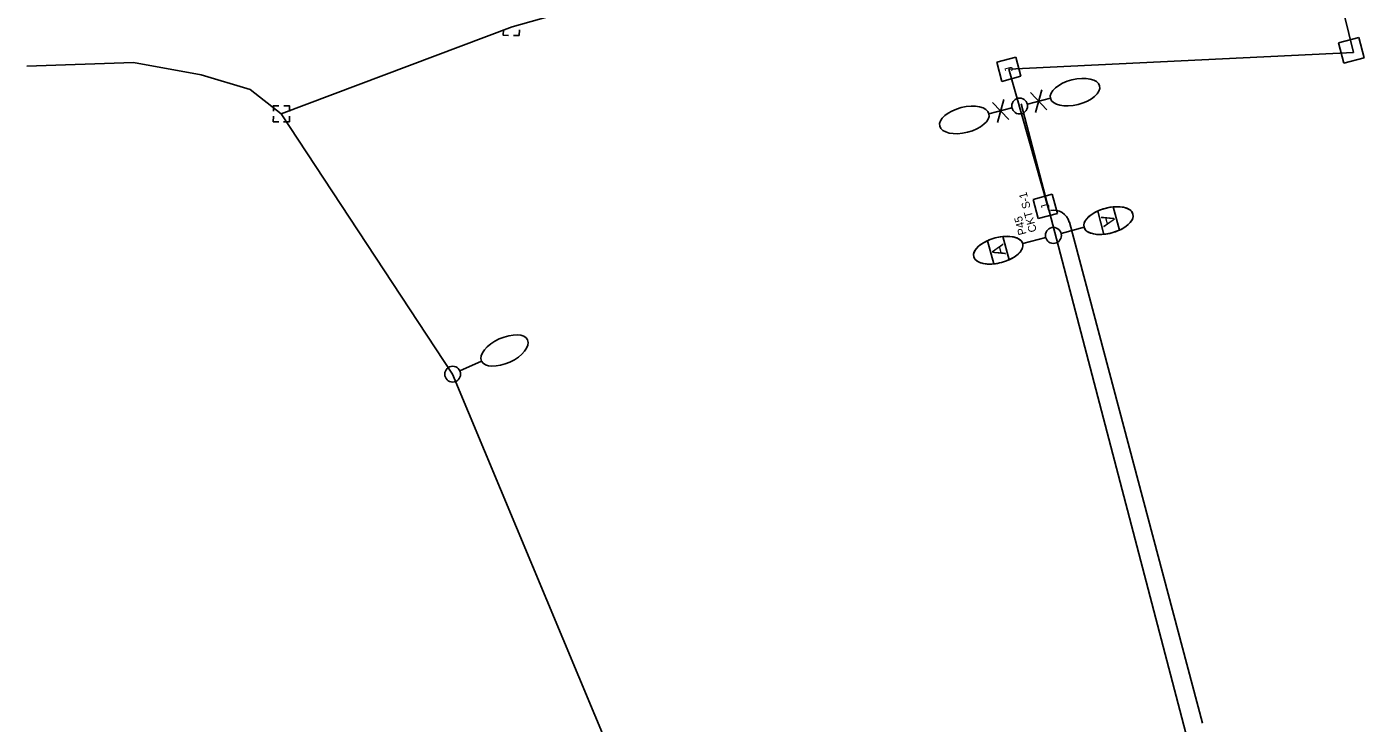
# Model space of a CAD drawing. Extents: x 925407 to 931638, y 609358 to 637063.
# Drawn here: x 930335.1 to 930752.9, y 629066.9 to 629284.3 of the extents above; entities that cross this region are included whole.
import ezdxf

# ---------------------------------------------------------------- set-up
doc = ezdxf.new("R2010")
doc.units = 0
for name, color, linetype in [('ActivePointCell_dp', 7, 'Continuous'), ('Conduit', 7, 'Continuous'), ('ConduitDB', 7, 'Continuous'), ('ConduitOT', 7, 'Continuous'), ('JunctBoxA', 7, 'Continuous'), ('LiteCond_ep', 7, 'Continuous'), ('Miscellaneous2', 7, 'Continuous'), ('PoleLight', 7, 'Continuous'), ('PoleLight_ep', 7, 'Continuous'), ('PullBox', 7, 'Continuous'), ('TextLabel', 7, 'Continuous')]:
    doc.layers.add(name, color=color, linetype=linetype)

msp = doc.modelspace()

# ---------------------------------------------------------------- linework, layer by layer
at = {"layer": 'Conduit'}
for p, q in [((930486.8, 629284.31), (930519.05, 629293.47)), ((930414.63, 629257.14), (930486.8, 629284.31)), ((930368.45, 629273.18), (930335.14, 629272.05)), ((930389.64, 629269.3), (930368.45, 629273.18)), ((930404.88, 629264.71), (930389.64, 629269.3)), ((930414.63, 629257.14), (930404.88, 629264.71)), ((930468.17, 629175.85), (930414.63, 629257.14)), ((930545.09, 628991.73), (930468.17, 629175.85))]:
    msp.add_line(p, q, dxfattribs=at)
at = {"layer": 'ConduitDB'}
for p, q in [((930749.58, 629276.27), (930702.37, 629466.49)), ((930641.88, 629271.04), (930749.58, 629276.27))]:
    msp.add_line(p, q, dxfattribs=at)
at = {"layer": 'ConduitOT'}
for p, q in [((930654.4, 629227.01), (930641.88, 629271.04)), ((930702.37, 629066.89), (930660.78, 629223.33))]:
    msp.add_line(p, q, dxfattribs=at)
msp.add_arc((930655.94, 629222.05), 5, 14.8905, 101.5073, dxfattribs=at)
at = {"layer": 'LiteCond_ep'}
msp.add_line((930645.69, 629260.21), (930714.73, 628997.07), dxfattribs=at)
at = {"layer": 'Miscellaneous2'}
for p, q in [((930669.63, 629226.77), (930669.63, 629226.77)), ((930669.63, 629226.77), (930671.57, 629219.51)), ((930676.4, 629220.8), (930674.46, 629228.06)), ((930674.46, 629228.06), (930674.46, 629228.06)), ((930641.98, 629211.57), (930640.03, 629218.83)), ((930640.03, 629218.83), (930640.03, 629218.83)), ((930635.2, 629217.53), (930635.2, 629217.53)), ((930635.2, 629217.53), (930637.15, 629210.28))]:
    msp.add_line(p, q, dxfattribs=at)
for centre, start_param, end_param in [((930673.01, 629223.79), 1.249648, 1.891946), ((930638.59, 629214.55), 1.249648, 1.891946), ((930673.01, 629223.79), 4.391271, 5.033538), ((930673.01, 629223.79), 4.391241, 4.391271), ((930638.59, 629214.55), 4.391271, 5.033538), ((930638.59, 629214.55), 4.391241, 4.391271)]:
    msp.add_ellipse(centre, major_axis=(7.65, 2.05), ratio=0.5, start_param=start_param, end_param=end_param, dxfattribs=at)
at = {"layer": 'PoleLight'}
for p, q in [((930671.57, 629219.51), (930669.63, 629226.77)), ((930674.46, 629228.06), (930676.4, 629220.8)), ((930640.03, 629218.83), (930641.98, 629211.57)), ((930653.41, 629218.53), (930646.24, 629216.6)), ((930658.19, 629219.81), (930665.36, 629221.73)), ((930637.15, 629210.28), (930635.2, 629217.53))]:
    msp.add_line(p, q, dxfattribs=at)
msp.add_circle((930655.8, 629219.17), 2.48, dxfattribs=at)
msp.add_circle((930655.8, 629219.17), 2.48, dxfattribs=at)
for centre in [(930673.01, 629223.79), (930638.59, 629214.55)]:
    msp.add_ellipse(centre, major_axis=(7.65, 2.05), ratio=0.5, dxfattribs=at)
for centre, start_param, end_param in [((930673.01, 629223.79), 1.891945, 4.391241), ((930673.01, 629223.79), 0.847605, 1.249648), ((930673.01, 629223.79), 0, 0.847605), ((930673.01, 629223.79), 5.033538, 6.283185), ((930638.59, 629214.55), 0.847605, 1.249648), ((930638.59, 629214.55), 0, 0.847605), ((930638.59, 629214.55), 1.891945, 4.391241), ((930638.59, 629214.55), 5.033538, 6.283185)]:
    msp.add_ellipse(centre, major_axis=(7.65, 2.05), ratio=0.5, start_param=start_param, end_param=end_param, dxfattribs=at)
at = {"layer": 'PoleLight_ep'}
for p, q in [((930652.21, 629264.66), (930650.17, 629257.52)), ((930636.77, 629260.7), (930641.93, 629255.37)), ((930638.33, 629254.46), (930640.37, 629261.6)), ((930647.67, 629260.16), (930654.87, 629261.97)), ((930653.77, 629258.42), (930648.61, 629263.75)), ((930642.87, 629258.96), (930635.67, 629257.15)), ((930470.42, 629176.87), (930477.17, 629179.95))]:
    msp.add_line(p, q, dxfattribs=at)
for centre in [(930645.27, 629259.56), (930468.17, 629175.85)]:
    msp.add_circle(centre, 2.48, dxfattribs=at)
for centre, major_axis in [((930662.56, 629263.9), (7.68, 1.93)), ((930627.99, 629255.22), (-7.68, -1.93)), ((930484.38, 629183.24), (7.21, 3.29))]:
    msp.add_ellipse(centre, major_axis=major_axis, ratio=0.5, dxfattribs=at)
at = {"layer": 'PullBox'}
for p, q in [((930744.88, 629279.3), (930751.21, 629280.98)), ((930751.21, 629280.98), (930752.89, 629274.65)), ((930746.56, 629272.97), (930744.88, 629279.3)), ((930638.09, 629273.23), (930644.08, 629274.83)), ((930639.69, 629267.25), (930638.09, 629273.23)), ((930644.08, 629274.83), (930645.67, 629268.84)), ((930752.89, 629274.65), (930746.56, 629272.97)), ((930645.67, 629268.84), (930639.69, 629267.25)), ((930649.47, 629230.42), (930655.46, 629232.01)), ((930651.06, 629224.43), (930649.47, 629230.42)), ((930655.46, 629232.01), (930657.05, 629226.02)), ((930657.05, 629226.02), (930651.06, 629224.43))]:
    msp.add_line(p, q, dxfattribs=at)
for points in [[(930484, 629283.37), (930483.98, 629281.64), (930485.66, 629281.62)], [(930487.21, 629281.61), (930488.98, 629281.59)], [(930488.98, 629281.59), (930489, 629283.32)], [(930413.88, 629259.66), (930412.2, 629259.67), (930412.19, 629257.91)], [(930417.19, 629257.87), (930417.2, 629259.63), (930415.43, 629259.64)], [(930412.17, 629256.41), (930412.16, 629254.68), (930413.83, 629254.66)], [(930417.16, 629254.63), (930417.17, 629256.37)], [(930415.38, 629254.65), (930417.16, 629254.63)]]:
    msp.add_lwpolyline(points, dxfattribs=at)

# ---------------------------------------------------------------- texts
at = {"layer": 'ActivePointCell_dp'}
for s, p in [('CKT S-1', (930650.65, 629220.5)), ('P45', (930647.41, 629219.65))]:
    msp.add_text(s, height=2.5, rotation=104.7826, dxfattribs=at).set_placement(p)
at = {"layer": 'JunctBoxA'}
for p in [(930643.3, 629270.54), (930654.67, 629227.73)]:
    msp.add_text('J', height=2.48, rotation=104.8905, dxfattribs=at).set_placement(p)
at = {"layer": 'TextLabel'}
for rotation, p in [(285.0135, (930670.6, 629225.07)), (105.0135, (930641, 629213.27))]:
    msp.add_text('A', height=4, rotation=rotation, dxfattribs=at).set_placement(p)

doc.saveas('drawing.dxf')
